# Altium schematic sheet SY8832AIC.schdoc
size 127 x 101 mm
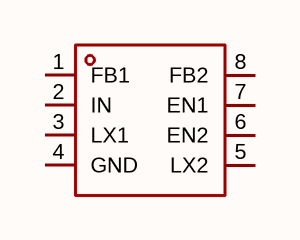
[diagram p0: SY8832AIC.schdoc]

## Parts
U?  sy8832aic  [TSOT-23-8_L2.9-W1.6-P0.65-LS2.8-BL]  (value not drawn)

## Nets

Not connected (* = marked no-connect by the designer): U? 1(FB1) 2(IN) 3(LX1) 4(GND) 5(LX2) 6(EN2) 7(EN1) 8(FB2)

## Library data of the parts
U? = sy8832aic: 功能类型:降压型;工作电压:2.5V~5.5V;输出电压:-;输出电流:2A;输出类型:可调;; Manufacturer: Silergy(矽力杰); AddInBom: yes; ModelId: dee2381274cf43f7a1d90e9872eb6b7d; ModelName: TSOT-23-8_L2.9-W1.6-H1.1-LS2.8-P0.65; ModelTransform: 110.45568,114.173,0,90,0,0,0,0,0; Function: 降压型; Output Current: 2A; Frequency - Switching: 2MHz; Synchronous Rectifier: 是; Number of Outputs: 2; Topology: 降压式; Quiescent Current: 45uA；35uA; Switch tube (built-in/external): 内置; Output Type: 可调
